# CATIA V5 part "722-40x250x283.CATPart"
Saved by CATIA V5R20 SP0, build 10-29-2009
Part number: 722-40x250x283
Definition: NONE
Nomenclature: 722-40x250x283
Source: Unknown
Description: 722-40x250x283
Bounding box of the stored display mesh (mm): x -20 to 20, y -20 to 20, z -235 to 48
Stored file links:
  C:\Users\Utente\Desktop\IO LAVORO\3D X SITO CF\X SITO\722\722-40x250x283.CATPart
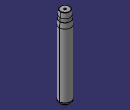
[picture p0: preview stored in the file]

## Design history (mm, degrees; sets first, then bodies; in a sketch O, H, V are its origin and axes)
Body1 "722-40x250x283" (main body)
  Solid1: solid without history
